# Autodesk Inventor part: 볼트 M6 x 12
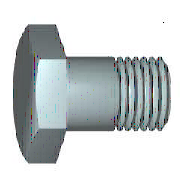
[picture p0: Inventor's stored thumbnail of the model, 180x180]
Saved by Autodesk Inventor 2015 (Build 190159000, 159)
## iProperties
IsCustomPart: 0
Created: 2012-02
Part Number: 볼트 M6 x 12
Material: 스테인리스강
Description: 6각 머리 나사. 제품 등급 C
Document SubType Name: Modeling
Standard: ISO 4018
Designer: mduedu
Standard Revision: Third edition 1999-08-15
Standards Organization: ISO
Language: ko-KR
Size Designation: M6 x 12
Categories: <MemberInstance><Categories><Category DisplayName="조임쇠" InternalName="e4da775c-781d-43d5-af7c-5136215cf5a6" Mnemonic="FSTN"><Category DisplayName="볼트" InternalN
Density: 8.08 g/cm^3
Appearance: 반광택
Author: mduedu
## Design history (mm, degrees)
node "WorkPlane1"
node "WorkPoint1"
node "MSC_A1"
node "MSC_PF1"
node "MSC_PT1"
body "Solid1"
node "스케치1"
sketch "스케치2"
  geometry: L1 (-5, 2.887)-(-5, -2.887); L2 (0, 5.773)-(-5, 2.887); L3 (5, 2.887)-(0, 5.773); L4 (5, -2.887)-(5, 2.887); L5 (0, -5.773)-(5, -2.887); L6 (-5, -2.887)-(0, -5.773); C1 r 5 at (0, 0); 1 further point
  constraints: 12 end point, 6 tangent, 2 parallel, 2 vertical, 1 centre point
  dimensions: "d1" = 10 diameter of C1 (= ParS); "d29" = 0 distance of point (0, 0) C1.centre; "d30" = 0 distance of C1.centre point (0, 0)
extrude "돌출1" new body sketch "스케치2" distance "d6" = 4 (= ParK); taper "d7" = 0 deg
revolve "회전1" stored, may be unused: angle "d14" = 360 deg
revolve "회전2" stored, may be unused: angle "d21" = 360 deg
chamfer "모따기1" distance "d22" = 0.5 (= 0.5 x PTC); stored, may be unused: second distance "d23" = 0.5 (= 0.5 x PTC), angle "d39" = 45 deg
fillet "모깎기1" dims "d24" = 0.25 (= r)
feature "스레드1" dims "d32" = 0, "b" = 10 (= NLG - 2 x PTC)
sketch "스케치3"
  geometry: L1 (5, 4)-(5.873, 4); L2 (5.873, 3.496)-(5, 4); L3 (5.873, 4)-(5.873, 3.496); L4 (0, -0.8)-(0, 4.8) reference; L5 (5.773, 0)-(5.773, 4) reference
  constraints: 6 end point, 1 horizontal, 1 vertical
  dimensions: "d25" = 0.1 distance between parallel lines of L5 L3; "d26" = 0 distance from line of L5.end L1; "d27" = 60 deg angle of L3 L2; "d28" = 5 distance from line of L4 L1.start (= 0.5 x ParS)
sketch "스케치4"
  geometry: L1 (0, -12)-(0, 0); L2 (-3, -12)-(0, -12); L3 (-3, 0)-(-3, -12); L4 (0, 0)-(-3, 0); L5 (0, -12)-(0, 0); L6 (-3.6, 0)-(0.6, 0) reference; L7 (0, -14.4)-(0, 2.4) reference
  constraints: 10 end point, 2 horizontal, 2 vertical
  dimensions: "d18" = 3 distance of L1.start L2.start (= 0.5 x NND); "d20" = 12 distance of L3.start L2.start (= NLG); "d33" = 0 distance between parallel lines of L7 L1; "d34" = 0 distance between parallel lines of L6 L4
other parameters: "NND" = 6 [user parameter; used in 2 equation terms], "NLG" = 12 [user parameter; used in 2 equation terms], "PTC" = 1 [user parameter; used in 3 equation terms], "ParK" = 4 [user parameter; used in 1 equation term], "ParS" = 10 [user parameter; used in 3 equation terms], "msp_es" = 5.77367 (= 0.577367 x ParS) [user parameter], "r" = 0.25 [user parameter; used in 1 equation term], "d2" = 15 (derived), "d4" = 17.32102 (derived), "d8" = 15 (derived), "d10" = 0 (derived), "d12" = 30 deg (derived), "d15" = 0 (derived), "d37" = 0, "d38" = 0, "d40" = 0, "d41" = 0, "d42" = 0, "THREADDIA" = 6 (= NND) [user parameter]
